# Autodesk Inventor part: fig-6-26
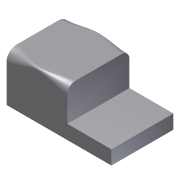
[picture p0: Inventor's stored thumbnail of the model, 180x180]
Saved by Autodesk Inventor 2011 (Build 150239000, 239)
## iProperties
Created: 2004-05
Part Number: fig-6-26
Document SubType Name: Modeling
Designer: CADCIM Technologies
Manufacturer: Standard
Standards Organization: Custom
Density: 1 g/cm^3
Author: CADCIM Technologies
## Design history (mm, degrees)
node "Sketch1"
sketch "Sketch2"
  geometry: L1 (0.098, 47.711)-(0.098, 0.049); L2 (0.098, 0.049)-(-105.483, 0.049); L3 (-105.483, 0.049)-(-105.483, 14.192); L4 (-105.483, 14.192)-(-61.139, 14.192); L5 (-61.139, 14.192)-(-61.139, 47.711); L6 (-61.139, 47.711)-(0.098, 47.711)
  constraints: 12 end point, 3 parallel, 2 perpendicular, 1 vertical
extrude "Extrusion1" new body sketch "Sketch2" stored distance "d0" = 62.5; taper "d1" = 0 deg
fillet "Fillet9" dims "d61" = 10, "d62" = 8, "d63" = 2, "d64" = 5
fillet "Fillet10" dims "d65" = 8, "d66" = 10, "d67" = 2, "d68" = 5
body "Solid1"
